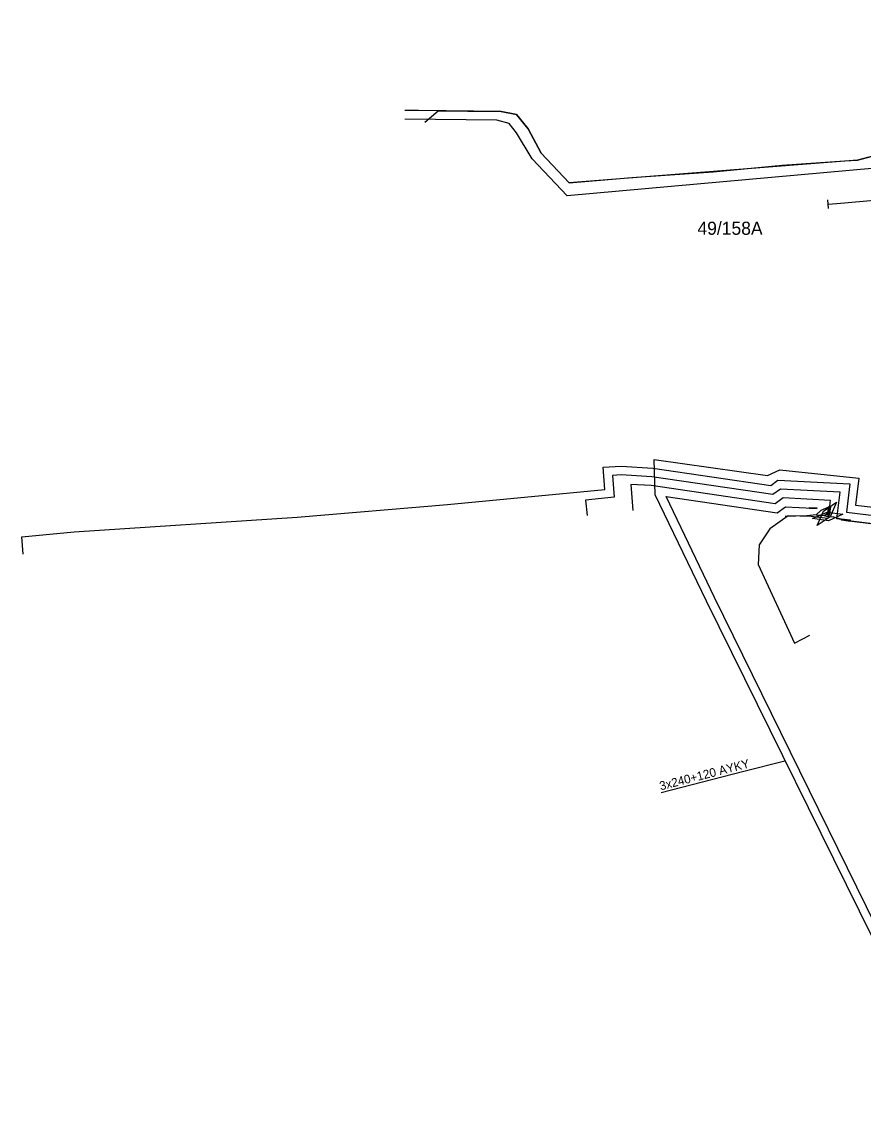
# Model space of a CAD drawing. Extents: x -744800 to -744528, y -1052473 to -1052336.
# Drawn here: x -744800.1 to -744703.7, y -1052473.4 to -1052347.4 of the extents above; entities that cross this region are included whole.
import ezdxf

# ---------------------------------------------------------------- set-up
doc = ezdxf.new("R2010")
doc.units = 0
for name, color, linetype in [('NN_KABEL_INSTALACE_RIS_PROVOZ', 7, 'Continuous'), ('NN_KABELOVE_VEDENI_PROVOZ', 7, 'Continuous'), ('NN_KABELOVE_VEDENI_VYRAZENO', 7, 'Continuous'), ('NN_POPIS_USEKU', 7, 'Continuous'), ('NN_PRIPOJOVACI_MISTO', 7, 'Continuous'), ('NN_RIS', 7, 'Continuous'), ('NN_SPOJKA', 7, 'Continuous'), ('TR_SPOJKOVISTE_NN', 7, 'Continuous'), ('TRASA_KABELU_NN_PROVOZ', 7, 'Continuous')]:
    doc.layers.add(name, color=color, linetype=linetype)

msp = doc.modelspace()

# ---------------------------------------------------------------- linework, layer by layer
at = {"layer": 'NN_KABEL_INSTALACE_RIS_PROVOZ'}
msp.add_line((-744706.7, -1052368.25), (-744701.93, -1052367.84), dxfattribs=at)
at = {"layer": 'NN_KABELOVE_VEDENI_PROVOZ'}
for points in [[(-744699.14, -1052349.26), (-744699.24, -1052347.43), (-744701.31, -1052347.43), (-744701.22, -1052349.22), (-744700.29, -1052362.2), (-744704.33, -1052363.29), (-744737.39, -1052365.89), (-744740.6, -1052362.49), (-744742.06, -1052359.67), (-744743.42, -1052358.06), (-744745.19, -1052357.69), (-744754.66, -1052357.57), (-744756.2, -1052357.58)], [(-744700.2, -1052349.24), (-744699.68, -1052357.72), (-744699.29, -1052363.92), (-744737.59, -1052367.36), (-744741.63, -1052363.13), (-744743.41, -1052360.15), (-744744.27, -1052359.09), (-744745.66, -1052358.69), (-744756.22, -1052358.58)], [(-744799.96, -1052408.48), (-744800.12, -1052406.5), (-744794.13, -1052405.93), (-744768.56, -1052404.24), (-744751.32, -1052402.79), (-744733.28, -1052401.05), (-744733.48, -1052398.51), (-744731.4, -1052398.39), (-744727.77, -1052398.62), (-744714.27, -1052400.59), (-744713.45, -1052400), (-744705.18, -1052400.42), (-744705.58, -1052403.66), (-744687.51, -1052405.82), (-744668.65, -1052404.71), (-744627.98, -1052399.75), (-744625.88, -1052400.49), (-744566.95, -1052393.58), (-744568.26, -1052383.97), (-744549.76, -1052382.66), (-744547.86, -1052381.46), (-744527.68, -1052380.35), (-744528.08, -1052374.98), (-744530.48, -1052375.1)], [(-744701.23, -1052459.94), (-744697.97, -1052462.01), (-744701.2, -1052455.31), (-744721.63, -1052413.86), (-744727.53, -1052401.67), (-744727.63, -1052397.6), (-744714.62, -1052399.45), (-744713.24, -1052398.8), (-744704.15, -1052399.75), (-744704.54, -1052402.84), (-744687.32, -1052404.81), (-744668.44, -1052403.65), (-744628.03, -1052398.74), (-744625.7, -1052399.46), (-744568.11, -1052392.69), (-744569.39, -1052383.09), (-744550.15, -1052381.71), (-744547.96, -1052380.35), (-744528.63, -1052379.39), (-744528.92, -1052376.5)], [(-744705.66, -1052404.56), (-744706.68, -1052404.43), (-744706.3, -1052401.37), (-744713.15, -1052401.02), (-744714.02, -1052401.64), (-744727.88, -1052399.62), (-744731.4, -1052399.39), (-744732.4, -1052399.45), (-744732.2, -1052401.95), (-744735.5, -1052402.27), (-744735.32, -1052404.04)], [(-744707.58, -1052403.53), (-744707.43, -1052402.31), (-744712.85, -1052402.03), (-744713.77, -1052402.69), (-744727.98, -1052400.61), (-744730.31, -1052400.47), (-744730.07, -1052403.45)], [(-744707.58, -1052403.53), (-744707.71, -1052404.38), (-744709.64, -1052404.17), (-744712.26, -1052404.07), (-744714.37, -1052405.56), (-744715.58, -1052407.42), (-744715.71, -1052409.67), (-744711.54, -1052418.69), (-744709.78, -1052417.75)], [(-744705.66, -1052404.56), (-744687.56, -1052406.82), (-744672.82, -1052405.92), (-744672.79, -1052407.76)]]:
    msp.add_lwpolyline(points, dxfattribs=at)
at = {"layer": 'NN_KABELOVE_VEDENI_VYRAZENO'}
msp.add_lwpolyline([(-744696.93, -1052473.39), (-744699.64, -1052468.55), (-744698.72, -1052468.08), (-744698.18, -1052467.88), (-744696.21, -1052462.84), (-744700.05, -1052455.55), (-744720.71, -1052413.45), (-744726.26, -1052401.87), (-744713.52, -1052403.73), (-744712.56, -1052403.05), (-744709.42, -1052403.19)], dxfattribs=at)
at = {"layer": 'NN_POPIS_USEKU'}
msp.add_lwpolyline([(-744726.82, -1052435.82), (-744717.5, -1052433.41), (-744712.65, -1052432.19)], dxfattribs=at)
at = {"layer": 'NN_PRIPOJOVACI_MISTO'}
for p, q in [((-744707.64, -1052368.83), (-744707.73, -1052367.84)), ((-744707.68, -1052368.33), (-744706.7, -1052368.25))]:
    msp.add_line(p, q, dxfattribs=at)
at = {"layer": 'NN_SPOJKA'}
for points in [[(-744707.74, -1052404.02), (-744707.6, -1052403.02), (-744707.42, -1052403.04), (-744707.56, -1052404.05)], [(-744709.81, -1052403.13), (-744708.98, -1052403.17), (-744708.98, -1052403.25), (-744709.82, -1052403.21), (-744709.82, -1052403.19), (-744709.04, -1052403.22), (-744709.04, -1052403.19), (-744709.81, -1052403.16)], [(-744706.15, -1052404.41), (-744705.14, -1052404.53), (-744705.16, -1052404.71), (-744706.17, -1052404.59)]]:
    msp.add_lwpolyline(points, close=True, dxfattribs=at)
at = {"layer": 'TR_SPOJKOVISTE_NN'}
for points in [[(-744708.95, -1052405.2), (-744708.21, -1052403.54), (-744706.71, -1052402.52), (-744707.45, -1052404.18), (-744708.95, -1052405.2)], [(-744709.46, -1052404.39), (-744707.8, -1052403.65), (-744706, -1052403.9), (-744707.66, -1052404.64), (-744709.46, -1052404.39)]]:
    msp.add_lwpolyline(points, dxfattribs=at)
at = {"layer": 'TRASA_KABELU_NN_PROVOZ'}
msp.add_line((-744709.05, -1052403.97), (-744708.15, -1052404.03), dxfattribs=at)
for points in [[(-744753.93, -1052358.92), (-744752.39, -1052357.63), (-744748.99, -1052357.66), (-744745.19, -1052357.69), (-744743.42, -1052358.06), (-744742.06, -1052359.67), (-744740.6, -1052362.49), (-744737.39, -1052365.89), (-744730.18, -1052365.27), (-744720.87, -1052364.6), (-744712.96, -1052363.84), (-744705.81, -1052363.36), (-744704.33, -1052363.29), (-744700.29, -1052362.2)], [(-744707.06, -1052404.21), (-744705.62, -1052404.63), (-744687.96, -1052406.76), (-744687.13, -1052406.69), (-744684.14, -1052406.54), (-744680.84, -1052406.36), (-744668.91, -1052405.67), (-744645.46, -1052402.88), (-744625.74, -1052400.54)], [(-744709.05, -1052403.97), (-744710.14, -1052404.08), (-744712.6, -1052404.17)], [(-744708.15, -1052404.03), (-744707.83, -1052403.86), (-744707.52, -1052403.39), (-744707.73, -1052403.12), (-744708.53, -1052403.47), (-744709.05, -1052403.97)], [(-744708.15, -1052404.03), (-744707.73, -1052404.14), (-744707.06, -1052404.21)]]:
    msp.add_lwpolyline(points, dxfattribs=at)

# ---------------------------------------------------------------- texts
at = {"layer": 'NN_POPIS_USEKU'}
msp.add_text('3x240+120 AYKY', height=1, rotation=14.5114, dxfattribs=at).set_placement((-744726.88, -1052435.58))
at = {"layer": 'NN_RIS'}
msp.add_text('49/158A', height=1.5, dxfattribs=at).set_placement((-744722.67, -1052371.84))

doc.saveas('drawing.dxf')
